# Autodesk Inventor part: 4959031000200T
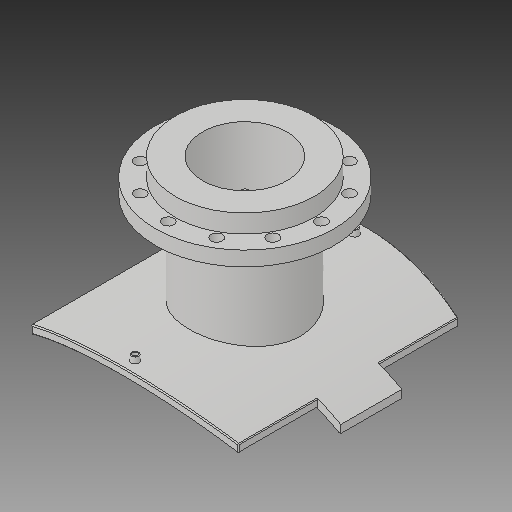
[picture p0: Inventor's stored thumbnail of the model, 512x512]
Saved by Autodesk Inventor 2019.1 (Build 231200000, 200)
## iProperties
Created: 2017-10
Part Number: 4959031000200T
Material: Generic
Description: PLASSON FLANGED BRANCH SADDLE 1000X200
Document SubType Name: Modeling
Designer: KIM
Mass: 2339.99 g
Surface Area: 3251.55 cm^2
Volume: 2339.99 cm^3
Density: 1 g/cm^3
Appearance: Default
Author: KIM
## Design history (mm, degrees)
derived "495904_495903.ipt"
feature "Solid1::495904_495903.ipt"
feature "Solid2::495904_495903.ipt"
tag "TaggingFeature1"
body "Solid1"
other parameters: "d1" = 15, "d2" = 398.7, "d4" = 0, "d6" = 117.5, "d7" = 0, "d12" = 525.6, "d13" = 14, "d14" = 211.5, "d16" = 5 deg, "d18" = 4, "d19" = 14, "d20" = 0, "d21" = 3, "d22" = 0, "d23" = 765, "d36" = 211.5, "d38" = 0, "d39" = 2, "d41" = 163, "d42" = 268, "d43" = 344, "d46" = 214.4, "d47" = 16, "d48" = 10.4, "d49" = 175, "d53" = 0, "d54" = 22, "d55" = 147.5, "d57" = 0, "d59" = 360 deg, "d61" = 28, "d63" = 0, "d67" = 15, "d68" = 125, "d70" = 0, "d71" = 2, "d72" = 443, "d_1" = 268, "B_" = 443, "x_" = 15, "D_" = 16, "DN_" = 163, "D_1" = 344, "t_" = 28, "s_" = 22, "Dp_" = 295
